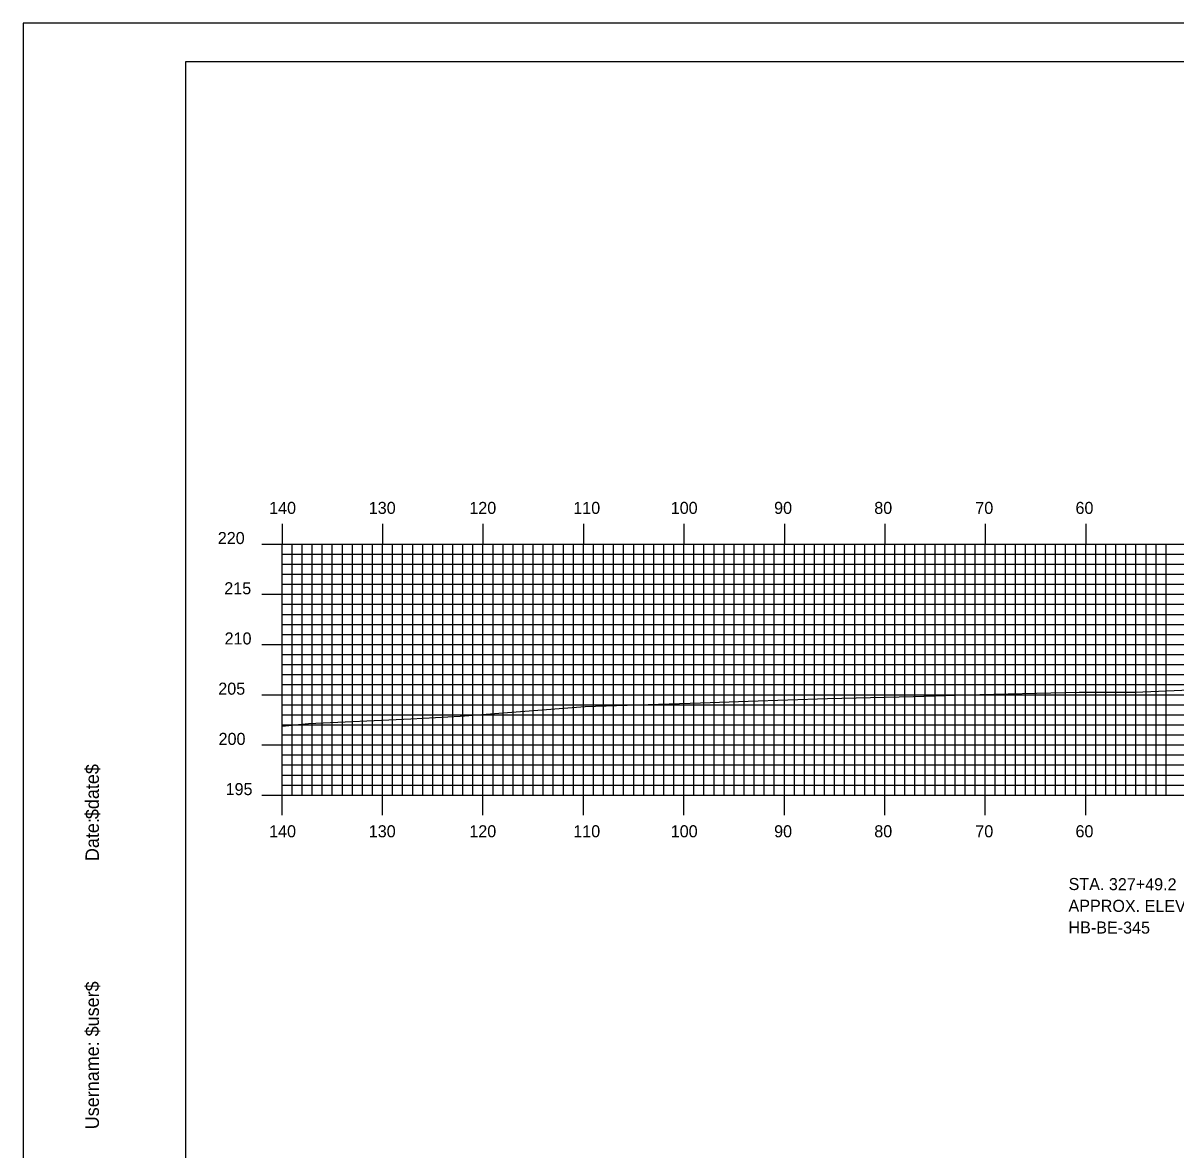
# Model space of a CAD drawing. Extents: x 1821605 to 1821948, y 442591 to 442811.
# Drawn here: x 1821605 to 1821719.7, y 442698.3 to 442810.5 of the extents above; entities that cross this region are included whole.
import ezdxf

# ---------------------------------------------------------------- set-up
doc = ezdxf.new("R2010")
doc.units = 0
for name, color, linetype in [('BORDER', 7, 'Continuous'), ('BORING - NO REFUSAL', 7, 'Continuous'), ('H_V ANNOTATION', 7, 'Continuous'), ('MAJOR', 7, 'Continuous'), ('MINOR', 7, 'Continuous'), ('PLOT BOUNDARY', 7, 'Continuous'), ('S_Roadway_Centerline', 7, 'Continuous')]:
    doc.layers.add(name, color=color, linetype=linetype)

msp = doc.modelspace()

# ---------------------------------------------------------------- linework, layer by layer
at = {"layer": 'BORDER'}
msp.add_lwpolyline([(1821621.14, 442596.67), (1821941.14, 442596.67), (1821941.14, 442806.67), (1821621.14, 442806.67)], close=True, dxfattribs=at)
at = {"layer": 'MAJOR'}
for p, q in [((1821630.74, 442760.67), (1821630.74, 442758.67)), ((1821640.74, 442760.67), (1821640.74, 442758.67)), ((1821650.74, 442760.67), (1821650.74, 442758.67)), ((1821660.74, 442760.67), (1821660.74, 442758.67)), ((1821670.74, 442760.67), (1821670.74, 442758.67)), ((1821680.74, 442760.67), (1821680.74, 442758.67)), ((1821690.74, 442760.67), (1821690.74, 442758.67)), ((1821700.74, 442760.67), (1821700.74, 442758.67)), ((1821710.74, 442760.67), (1821710.74, 442758.67)), ((1821628.74, 442758.67), (1821630.74, 442758.67)), ((1821630.74, 442758.67), (1821910.74, 442758.67)), ((1821630.74, 442733.67), (1821630.74, 442758.67)), ((1821630.74, 442733.67), (1821630.74, 442758.67)), ((1821630.74, 442758.67), (1821910.74, 442758.67)), ((1821640.74, 442733.67), (1821640.74, 442758.67)), ((1821650.74, 442733.67), (1821650.74, 442758.67)), ((1821660.74, 442733.67), (1821660.74, 442758.67)), ((1821670.74, 442733.67), (1821670.74, 442758.67)), ((1821680.74, 442733.67), (1821680.74, 442758.67)), ((1821690.74, 442733.67), (1821690.74, 442758.67)), ((1821700.74, 442733.67), (1821700.74, 442758.67)), ((1821710.74, 442733.67), (1821710.74, 442758.67)), ((1821628.74, 442753.67), (1821630.74, 442753.67)), ((1821630.74, 442753.67), (1821910.74, 442753.67)), ((1821628.74, 442748.67), (1821630.74, 442748.67)), ((1821630.74, 442748.67), (1821910.74, 442748.67)), ((1821628.74, 442743.67), (1821630.74, 442743.67)), ((1821630.74, 442743.67), (1821910.74, 442743.67)), ((1821628.74, 442738.67), (1821630.74, 442738.67)), ((1821630.74, 442738.67), (1821910.74, 442738.67)), ((1821628.74, 442733.67), (1821630.74, 442733.67)), ((1821630.74, 442733.67), (1821910.74, 442733.67)), ((1821630.74, 442733.67), (1821910.74, 442733.67)), ((1821630.74, 442731.66), (1821630.74, 442733.67)), ((1821640.74, 442731.66), (1821640.74, 442733.67)), ((1821650.74, 442731.66), (1821650.74, 442733.67)), ((1821660.74, 442731.66), (1821660.74, 442733.67)), ((1821670.74, 442731.66), (1821670.74, 442733.67)), ((1821680.74, 442731.66), (1821680.74, 442733.67)), ((1821690.74, 442731.66), (1821690.74, 442733.67)), ((1821700.74, 442731.66), (1821700.74, 442733.67)), ((1821710.74, 442731.66), (1821710.74, 442733.67))]:
    msp.add_line(p, q, dxfattribs=at)
at = {"layer": 'MINOR'}
for p, q in [((1821631.74, 442733.67), (1821631.74, 442758.67)), ((1821632.74, 442733.67), (1821632.74, 442758.67)), ((1821633.74, 442733.67), (1821633.74, 442758.67)), ((1821634.74, 442733.67), (1821634.74, 442758.67)), ((1821635.74, 442733.67), (1821635.74, 442758.67)), ((1821636.74, 442733.67), (1821636.74, 442758.67)), ((1821637.74, 442733.67), (1821637.74, 442758.67)), ((1821638.74, 442733.67), (1821638.74, 442758.67)), ((1821639.74, 442733.67), (1821639.74, 442758.67)), ((1821641.74, 442733.67), (1821641.74, 442758.67)), ((1821642.74, 442733.67), (1821642.74, 442758.67)), ((1821643.74, 442733.67), (1821643.74, 442758.67)), ((1821644.74, 442733.67), (1821644.74, 442758.67)), ((1821645.74, 442733.67), (1821645.74, 442758.67)), ((1821646.74, 442733.67), (1821646.74, 442758.67)), ((1821647.74, 442733.67), (1821647.74, 442758.67)), ((1821648.74, 442733.67), (1821648.74, 442758.67)), ((1821649.74, 442733.67), (1821649.74, 442758.67)), ((1821651.74, 442733.67), (1821651.74, 442758.67)), ((1821652.74, 442733.67), (1821652.74, 442758.67)), ((1821653.74, 442733.67), (1821653.74, 442758.67)), ((1821654.74, 442733.67), (1821654.74, 442758.67)), ((1821655.74, 442733.67), (1821655.74, 442758.67)), ((1821656.74, 442733.67), (1821656.74, 442758.67)), ((1821657.74, 442733.67), (1821657.74, 442758.67)), ((1821658.74, 442733.67), (1821658.74, 442758.67)), ((1821659.74, 442733.67), (1821659.74, 442758.67)), ((1821661.74, 442733.67), (1821661.74, 442758.67)), ((1821662.74, 442733.67), (1821662.74, 442758.67)), ((1821663.74, 442733.67), (1821663.74, 442758.67)), ((1821664.74, 442733.67), (1821664.74, 442758.67)), ((1821665.74, 442733.67), (1821665.74, 442758.67)), ((1821666.74, 442733.67), (1821666.74, 442758.67)), ((1821667.74, 442733.67), (1821667.74, 442758.67)), ((1821668.74, 442733.67), (1821668.74, 442758.67)), ((1821669.74, 442733.67), (1821669.74, 442758.67)), ((1821671.74, 442733.67), (1821671.74, 442758.67)), ((1821672.74, 442733.67), (1821672.74, 442758.67)), ((1821673.74, 442733.67), (1821673.74, 442758.67)), ((1821674.74, 442733.67), (1821674.74, 442758.67)), ((1821675.74, 442733.67), (1821675.74, 442758.67)), ((1821676.74, 442733.67), (1821676.74, 442758.67)), ((1821677.74, 442733.67), (1821677.74, 442758.67)), ((1821678.74, 442733.67), (1821678.74, 442758.67)), ((1821679.74, 442733.67), (1821679.74, 442758.67)), ((1821681.74, 442733.67), (1821681.74, 442758.67)), ((1821682.74, 442733.67), (1821682.74, 442758.67)), ((1821683.74, 442733.67), (1821683.74, 442758.67)), ((1821684.74, 442733.67), (1821684.74, 442758.67)), ((1821685.74, 442733.67), (1821685.74, 442758.67)), ((1821686.74, 442733.67), (1821686.74, 442758.67)), ((1821687.74, 442733.67), (1821687.74, 442758.67)), ((1821688.74, 442733.67), (1821688.74, 442758.67)), ((1821689.74, 442733.67), (1821689.74, 442758.67)), ((1821691.74, 442733.67), (1821691.74, 442758.67)), ((1821692.74, 442733.67), (1821692.74, 442758.67)), ((1821693.74, 442733.67), (1821693.74, 442758.67)), ((1821694.74, 442733.67), (1821694.74, 442758.67)), ((1821695.74, 442733.67), (1821695.74, 442758.67)), ((1821696.74, 442733.67), (1821696.74, 442758.67)), ((1821697.74, 442733.67), (1821697.74, 442758.67)), ((1821698.74, 442733.67), (1821698.74, 442758.67)), ((1821699.74, 442733.67), (1821699.74, 442758.67)), ((1821701.74, 442733.67), (1821701.74, 442758.67)), ((1821702.74, 442733.67), (1821702.74, 442758.67)), ((1821703.74, 442733.67), (1821703.74, 442758.67)), ((1821704.74, 442733.67), (1821704.74, 442758.67)), ((1821705.74, 442733.67), (1821705.74, 442758.67)), ((1821706.74, 442733.67), (1821706.74, 442758.67)), ((1821707.74, 442733.67), (1821707.74, 442758.67)), ((1821708.74, 442733.67), (1821708.74, 442758.67)), ((1821709.74, 442733.67), (1821709.74, 442758.67)), ((1821711.74, 442733.67), (1821711.74, 442758.67)), ((1821712.74, 442733.67), (1821712.74, 442758.67)), ((1821713.74, 442733.67), (1821713.74, 442758.67)), ((1821714.74, 442733.67), (1821714.74, 442758.67)), ((1821715.74, 442733.67), (1821715.74, 442758.67)), ((1821716.74, 442733.67), (1821716.74, 442758.67)), ((1821717.74, 442733.67), (1821717.74, 442758.67)), ((1821718.74, 442733.67), (1821718.74, 442758.67)), ((1821630.74, 442757.67), (1821910.74, 442757.67)), ((1821630.74, 442757.67), (1821632.75, 442757.67)), ((1821630.74, 442756.67), (1821910.74, 442756.67)), ((1821630.74, 442756.67), (1821632.75, 442756.67)), ((1821630.74, 442755.67), (1821910.74, 442755.67)), ((1821630.74, 442755.67), (1821632.75, 442755.67)), ((1821630.74, 442754.67), (1821910.74, 442754.67)), ((1821630.74, 442754.67), (1821632.75, 442754.67)), ((1821630.74, 442752.67), (1821910.74, 442752.67)), ((1821630.74, 442752.67), (1821632.75, 442752.67)), ((1821630.74, 442751.67), (1821910.74, 442751.67)), ((1821630.74, 442751.67), (1821632.75, 442751.67)), ((1821630.74, 442750.67), (1821910.74, 442750.67)), ((1821630.74, 442750.67), (1821632.75, 442750.67)), ((1821630.74, 442749.67), (1821910.74, 442749.67)), ((1821630.74, 442749.67), (1821632.75, 442749.67)), ((1821630.74, 442747.67), (1821910.74, 442747.67)), ((1821630.74, 442747.67), (1821632.75, 442747.67)), ((1821630.74, 442746.67), (1821910.74, 442746.67)), ((1821630.74, 442746.67), (1821632.75, 442746.67)), ((1821630.74, 442745.67), (1821910.74, 442745.67)), ((1821630.74, 442745.67), (1821632.75, 442745.67)), ((1821630.74, 442744.67), (1821910.74, 442744.67)), ((1821630.74, 442744.67), (1821632.75, 442744.67)), ((1821630.74, 442742.67), (1821910.74, 442742.67)), ((1821630.74, 442742.67), (1821632.75, 442742.67)), ((1821630.74, 442741.67), (1821910.74, 442741.67)), ((1821630.74, 442741.67), (1821632.75, 442741.67)), ((1821630.74, 442740.67), (1821910.74, 442740.67)), ((1821630.74, 442740.67), (1821632.75, 442740.67)), ((1821630.74, 442739.67), (1821910.74, 442739.67)), ((1821630.74, 442739.67), (1821632.75, 442739.67)), ((1821630.74, 442737.67), (1821910.74, 442737.67)), ((1821630.74, 442737.67), (1821632.75, 442737.67)), ((1821630.74, 442736.67), (1821910.74, 442736.67)), ((1821630.74, 442736.67), (1821632.75, 442736.67)), ((1821630.74, 442735.67), (1821910.74, 442735.67)), ((1821630.74, 442735.67), (1821632.75, 442735.67)), ((1821630.74, 442734.67), (1821910.74, 442734.67)), ((1821630.74, 442734.67), (1821632.75, 442734.67))]:
    msp.add_line(p, q, dxfattribs=at)
at = {"layer": 'PLOT BOUNDARY'}
msp.add_lwpolyline([(1821604.96, 442590.55), (1821944.96, 442590.55), (1821944.96, 442810.55), (1821604.96, 442810.55)], close=True, dxfattribs=at)
at = {"layer": 'S_Roadway_Centerline'}
msp.add_lwpolyline([(1821630.74, 442740.53), (1821633.37, 442740.81), (1821643.56, 442741.25), (1821648.47, 442741.53), (1821660.92, 442742.48), (1821672.39, 442742.85), (1821677.12, 442743.03), (1821685.04, 442743.28), (1821693.58, 442743.5), (1821698.77, 442743.67), (1821710.09, 442743.92), (1821715.67, 442743.93), (1821723.41, 442744.25)], dxfattribs=at)

# ---------------------------------------------------------------- texts
at = {"layer": 'BORDER'}
for s, p in [('$date$', (1821612.51, 442731.28)), ('Date:', (1821612.51, 442727.1)), ('$user$', (1821612.51, 442709.65)), ('Username:', (1821612.51, 442700.4))]:
    msp.add_text(s, height=1.339, rotation=90, dxfattribs=at).set_placement(p)
at = {"layer": 'BORING - NO REFUSAL'}
for s, p in [('STA. 327+49.2', (1821709.03, 442724.22)), ('APPROX. ELEV. 183.9', (1821709.02, 442722.06)), ('HB-BE-345', (1821709.02, 442719.9))]:
    msp.add_text(s, height=1.2, rotation=359.8142, dxfattribs=at).set_placement(p)
at = {"layer": 'H_V ANNOTATION'}
for s, p in [('140', (1821629.45, 442761.67)), ('130', (1821639.37, 442761.67)), ('120', (1821649.38, 442761.67)), ('110', (1821659.73, 442761.67)), ('100', (1821669.43, 442761.67)), ('90', (1821679.72, 442761.67)), ('80', (1821689.69, 442761.67)), ('70', (1821699.75, 442761.67)), ('60', (1821709.72, 442761.67)), ('220', (1821624.34, 442758.67)), ('215', (1821624.99, 442753.67)), ('210', (1821625.02, 442748.67)), ('205', (1821624.39, 442743.67)), ('200', (1821624.42, 442738.67)), ('195', (1821625.12, 442733.67)), ('140', (1821629.45, 442729.47)), ('130', (1821639.37, 442729.47)), ('120', (1821649.38, 442729.47)), ('110', (1821659.73, 442729.47)), ('100', (1821669.43, 442729.47)), ('90', (1821679.72, 442729.47)), ('80', (1821689.69, 442729.47)), ('70', (1821699.75, 442729.47)), ('60', (1821709.72, 442729.47))]:
    msp.add_text(s, height=1.2, dxfattribs=at).set_placement(p)
at = {"layer": 'MAJOR'}
msp.add_text('-', height=0.012, dxfattribs=at).set_placement((1821630.73, 442733.67))

doc.saveas('drawing.dxf')
